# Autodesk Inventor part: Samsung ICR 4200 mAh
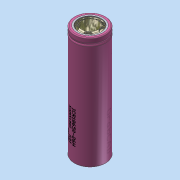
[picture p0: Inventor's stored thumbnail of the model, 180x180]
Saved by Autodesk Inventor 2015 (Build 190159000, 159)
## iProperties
Created: 2020-11
Part Number: Samsung ICR 4200 mAh
Material: Generic
Document SubType Name: Modeling
Designer: Egi Rahmadi Kusuma
Density: 1 g/cm^3
Appearance: Default
Author: Egi Rahmadi Kusuma
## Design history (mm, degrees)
sketch "Sketch1"
  geometry: L1 (6.6, 0)-(8.6, 0); L2 (9.1, 0.5)-(9.1, 64.5); L3 (0, 65)-(0, 0.2); L4 (7.5, 65)-(7.5, 64.99); L5 (7.5, 64.99)-(6.6, 64.99); L6 (6.5, 64.89)-(6.5, 64.59); L7 (6.6, 64.49)-(7, 64.49); L8 (7, 64.49)-(7.643, 63.724); L9 (7.643, 63.724)-(6.609, 63.724); L10 (5.843, 64.081)-(5.372, 64.643); L11 (8.6, 65)-(7.5, 65); L12 (4.606, 65)-(0, 65); L13 (6.6, 0)-(6.6, 0.2); L14 (6.6, 0.2)-(0, 0.2); A1 r 1.8 centre (7.3, 62.495) between (8.8, 61.5) and (9.1, 62.5); A2 r 1.8 centre (7.3, 60.505) between (9.1, 60.5) and (8.8, 61.5); A3 r 0.5 centre (8.6, 64.5) between (9.1, 64.5) and (8.6, 65); A4 r 0.5 centre (8.6, 0.5) between (8.6, 0) and (9.1, 0.5); A5 r 1 centre (4.606, 64) between (5.372, 64.643) and (4.606, 65); A6 r 1 centre (6.609, 64.724) between (5.843, 64.081) and (6.609, 63.724); A7 r 0.1 centre (6.6, 64.89) between (6.6, 64.99) and (6.5, 64.89); A8 r 0.1 centre (6.6, 64.59) between (6.5, 64.59) and (6.6, 64.49); 7 further points
  constraints: 28 end point, 16 point on circle, 14 point on line, 12 tangent, 8 centre point, 5 parallel, 3 horizontal, 3 perpendicular, 2 equal radius, 2 vertical
  dimensions: "d0" = 9.1 distance of L3.start point (9.1, 65); "d1" = 65 distance of point (9.1, 65) point (9.1, 0); "d3" = 0.3 distance from line of L2 A1.start; "d4" = 1.8 radius of A1; "d5" = 1.8 radius of A2; "d6" = 0.01 distance of L4.start L4.end; "d8" = 1.6 distance between parallel lines of L2 L4; "d9" = 1 distance of L4.end point (6.5, 64.99); "d10" = 0.5 distance of point (6.5, 64.99) point (6.5, 64.49); "d11" = 1 vertical distance of A1.end A1.start; "d12" = 1 vertical distance of A2.start A1.start; "d13" = 0.5 distance of point (6.5, 64.49) L7.end; "d14" = 1 distance of L7.end L8.end; "d15" = 130 deg angle of L7 L8; "d16" = 1.5 distance of L8.end point (6.143, 63.724); "d17" = 5.07206 distance from line of L3 point (5.072, 65) (derived); "d18" = 1.42794 distance from line of L6 point (5.072, 65); "d19" = 0.2 distance of L1.start L13.end; "d20" = 2.5 distance between parallel lines of L2 L13; "d21" = 64.8 distance of L3.start L3.end (derived); "d22" = 6.6 distance of L13.end L3.end (derived); "d24" = 0.5 radius of A3; "d25" = 1 radius of A5; "d26" = 1 radius of A6; "d34" = 0.1 radius of A7
revolve "Revolution1" sketch "Sketch1" stored, may be unused: angle "d23" = 90 deg
sketch "Sketch3"
  geometry: 2 further points; 1 other entity
  constraints: 2 other
extrude "Extrusion1" cut sketch "Sketch3" distance "d27" = 1.5; taper "d28" = 0 deg
workaxis "Work Axis1"
pattern_circular "Circular Pattern1" dims angle "d30" = 360 deg
sketch "Sketch4"
  geometry: C1 r 6.323 at (0, 5.185); 1 further point
  constraints: 1 centre point, 1 coincident
extrude "Extrusion2" cut sketch "Sketch4" stored distance "d32" = 0.5; taper "d33" = 0 deg
fillet "Fillet2" dims "d36" = 0.15
workplane "Work Plane1"
sketch "Sketch5"
  geometry: L1 (-27.245, 30.323)-(27.245, 30.323); L2 (27.245, 30.323)-(27.245, -31.568); L3 (27.245, -31.568)-(-27.245, -31.568); L4 (-27.245, -31.568)-(-27.245, 30.323); 2 further points; 1 other entity
  constraints: 1 midpoint, 1 vertical alignment, 2 other
feature "Decal1" sketch "Sketch5"
body "Solid1"
node "Image1"
other parameters: "d2" = 3.5
